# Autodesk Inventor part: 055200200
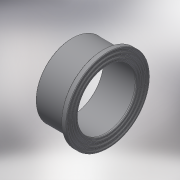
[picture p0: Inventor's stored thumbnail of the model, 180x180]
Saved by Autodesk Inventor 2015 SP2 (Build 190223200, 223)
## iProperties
Created: 2017-10
Part Number: 055200200
Material: Generic
Description: PLASSON FLANGE(FLAT GASKET)C 200
Document SubType Name: Modeling
Designer: KIM
Density: 1 g/cm^3
Appearance: Default
Author: KIM
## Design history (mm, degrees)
derived "055200.ipt"
feature "Solid1::055200.ipt"
tag "TaggingFeature1"
body "Solid1"
other parameters: "d0" = 114, "d1" = 228, "d4" = 19, "d5" = 106, "d6" = 254, "d8" = 5.7, "d11" = 2, "d12" = 2.85, "E_" = 228, "E_1" = 254, "l_" = 106, "B_" = 19, "H_" = 114, "d14" = 32
